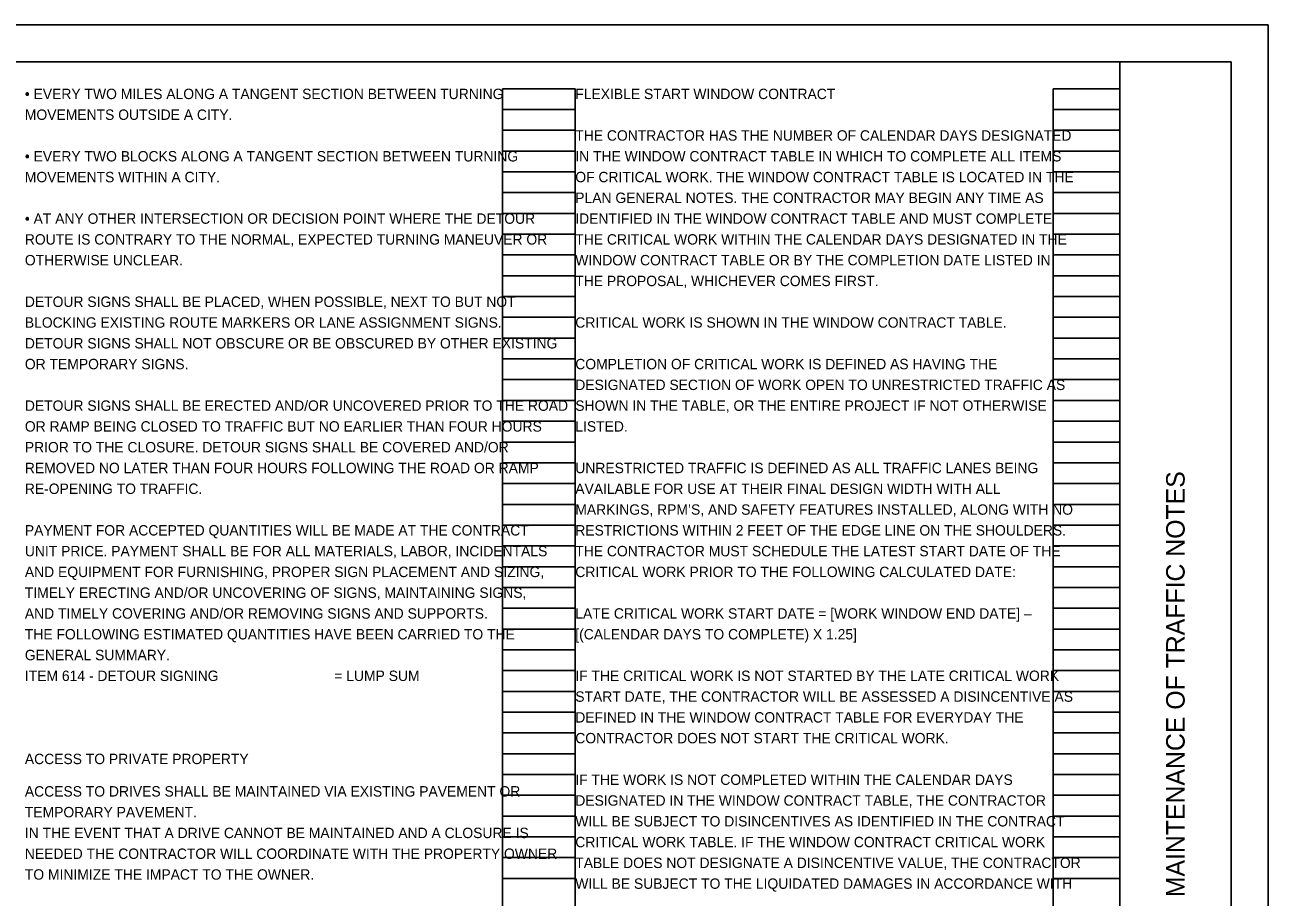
# Model space of a CAD drawing. Extents: x -1.3 to 43.7, y -2.4 to 22.
# Drawn here: x 17.24 to 34, y 10.25 to 22 of the extents above; entities that cross this region are included whole.
import ezdxf

# ---------------------------------------------------------------- set-up
doc = ezdxf.new("R2010")
doc.units = 0
for name, color, linetype in [('SH_Border', 7, 'Continuous'), ('SH_Cut_Line', 7, 'Continuous'), ('SH_Data', 7, 'Continuous'), ('SH_Text', 7, 'Continuous')]:
    doc.layers.add(name, color=color, linetype=linetype)

msp = doc.modelspace()

# ---------------------------------------------------------------- linework, layer by layer
at = {"layer": 'SH_Border'}
msp.add_line((32, 0.5), (32, 21.5), dxfattribs=at)
msp.add_lwpolyline([(1.5, 21.5), (33.5, 21.5), (33.5, 0.5), (1.5, 0.5)], close=True, dxfattribs=at)
at = {"layer": 'SH_Cut_Line'}
msp.add_lwpolyline([(0, 0), (34, 0), (34, 22), (0, 22)], close=True, dxfattribs=at)
at = {"layer": 'SH_Data'}
for p, q in [((23.68, 0.98), (23.68, 21.14)), ((23.68, 21.14), (24.66, 21.14)), ((24.66, 0.98), (24.66, 21.14)), ((31.1, 0.98), (31.1, 21.14)), ((31.1, 21.14), (32, 21.14)), ((32, 0.98), (32, 21.14)), ((23.68, 20.86), (24.66, 20.86)), ((31.1, 20.86), (32, 20.86)), ((23.68, 20.58), (24.66, 20.58)), ((31.1, 20.58), (32, 20.58)), ((23.68, 20.3), (24.66, 20.3)), ((31.1, 20.3), (32, 20.3)), ((23.68, 20.02), (24.66, 20.02)), ((31.1, 20.02), (32, 20.02)), ((23.68, 19.74), (24.66, 19.74)), ((31.1, 19.74), (32, 19.74)), ((23.68, 19.46), (24.66, 19.46)), ((31.1, 19.46), (32, 19.46)), ((23.68, 19.18), (24.66, 19.18)), ((31.1, 19.18), (32, 19.18)), ((23.68, 18.9), (24.66, 18.9)), ((31.1, 18.9), (32, 18.9)), ((23.68, 18.62), (24.66, 18.62)), ((31.1, 18.62), (32, 18.62)), ((23.68, 18.34), (24.66, 18.34)), ((31.1, 18.34), (32, 18.34)), ((23.68, 18.06), (24.66, 18.06)), ((31.1, 18.06), (32, 18.06)), ((23.68, 17.78), (24.66, 17.78)), ((31.1, 17.78), (32, 17.78)), ((23.68, 17.5), (24.66, 17.5)), ((31.1, 17.5), (32, 17.5)), ((23.68, 17.22), (24.66, 17.22)), ((31.1, 17.22), (32, 17.22)), ((23.68, 16.94), (24.66, 16.94)), ((31.1, 16.94), (32, 16.94)), ((23.68, 16.66), (24.66, 16.66)), ((31.1, 16.66), (32, 16.66)), ((23.68, 16.38), (24.66, 16.38)), ((31.1, 16.38), (32, 16.38)), ((23.68, 16.1), (24.66, 16.1)), ((31.1, 16.1), (32, 16.1)), ((23.68, 15.82), (24.66, 15.82)), ((31.1, 15.82), (32, 15.82)), ((23.68, 15.54), (24.66, 15.54)), ((31.1, 15.54), (32, 15.54)), ((23.68, 15.26), (24.66, 15.26)), ((31.1, 15.26), (32, 15.26)), ((23.68, 14.98), (24.66, 14.98)), ((31.1, 14.98), (32, 14.98)), ((23.68, 14.7), (24.66, 14.7)), ((31.1, 14.7), (32, 14.7)), ((23.68, 14.42), (24.66, 14.42)), ((31.1, 14.42), (32, 14.42)), ((23.68, 14.14), (24.66, 14.14)), ((31.1, 14.14), (32, 14.14)), ((23.68, 13.86), (24.66, 13.86)), ((31.1, 13.86), (32, 13.86)), ((23.68, 13.58), (24.66, 13.58)), ((31.1, 13.58), (32, 13.58)), ((23.68, 13.3), (24.66, 13.3)), ((31.1, 13.3), (32, 13.3)), ((23.68, 13.02), (24.66, 13.02)), ((31.1, 13.02), (32, 13.02)), ((23.68, 12.74), (24.66, 12.74)), ((31.1, 12.74), (32, 12.74)), ((23.68, 12.46), (24.66, 12.46)), ((31.1, 12.46), (32, 12.46)), ((23.68, 12.18), (24.66, 12.18)), ((31.1, 12.18), (32, 12.18)), ((23.68, 11.9), (24.66, 11.9)), ((31.1, 11.9), (32, 11.9)), ((23.68, 11.62), (24.66, 11.62)), ((31.1, 11.62), (32, 11.62)), ((23.68, 11.34), (24.66, 11.34)), ((31.1, 11.34), (32, 11.34)), ((23.68, 11.06), (24.66, 11.06)), ((31.1, 11.06), (32, 11.06)), ((23.68, 10.78), (24.66, 10.78)), ((31.1, 10.78), (32, 10.78)), ((23.68, 10.5), (24.66, 10.5)), ((31.1, 10.5), (32, 10.5))]:
    msp.add_line(p, q, dxfattribs=at)

# ---------------------------------------------------------------- texts
msp.add_text('MAINTENANCE OF TRAFFIC NOTES', height=0.25, rotation=90, dxfattribs=at).set_placement((32.875, 10.247))
at = {"layer": 'SH_Text'}
for s, p in [('• EVERY TWO MILES ALONG A TANGENT SECTION BETWEEN TURNING ', (17.24, 21)), ('FLEXIBLE START WINDOW CONTRACT', (24.66, 21)), ('MOVEMENTS OUTSIDE A CITY.', (17.24, 20.72)), ('THE CONTRACTOR HAS THE NUMBER OF CALENDAR DAYS DESIGNATED ', (24.66, 20.44)), ('• EVERY TWO BLOCKS ALONG A TANGENT SECTION BETWEEN TURNING ', (17.24, 20.16)), ('IN THE WINDOW CONTRACT TABLE IN WHICH TO COMPLETE ALL ITEMS ', (24.66, 20.16)), ('MOVEMENTS WITHIN A CITY.', (17.24, 19.88)), ('OF CRITICAL WORK. THE WINDOW CONTRACT TABLE IS LOCATED IN THE ', (24.66, 19.88)), ('PLAN GENERAL NOTES. THE CONTRACTOR MAY BEGIN ANY TIME AS ', (24.66, 19.6)), ('• AT ANY OTHER INTERSECTION OR DECISION POINT WHERE THE DETOUR ', (17.24, 19.32)), ('IDENTIFIED IN THE WINDOW CONTRACT TABLE AND MUST COMPLETE ', (24.66, 19.32)), ('ROUTE IS CONTRARY TO THE NORMAL, EXPECTED TURNING MANEUVER OR ', (17.24, 19.04)), ('THE CRITICAL WORK WITHIN THE CALENDAR DAYS DESIGNATED IN THE ', (24.66, 19.04)), ('OTHERWISE UNCLEAR.', (17.24, 18.76)), ('WINDOW CONTRACT TABLE OR BY THE COMPLETION DATE LISTED IN ', (24.66, 18.76)), ('THE PROPOSAL, WHICHEVER COMES FIRST.', (24.66, 18.48)), ('DETOUR SIGNS SHALL BE PLACED, WHEN POSSIBLE, NEXT TO BUT NOT ', (17.24, 18.2)), ('BLOCKING EXISTING ROUTE MARKERS OR LANE ASSIGNMENT SIGNS.  ', (17.24, 17.92)), ('CRITICAL WORK IS SHOWN IN THE WINDOW CONTRACT TABLE.', (24.66, 17.92)), ('DETOUR SIGNS SHALL NOT OBSCURE OR BE OBSCURED BY OTHER EXISTING ', (17.24, 17.64)), ('OR TEMPORARY SIGNS.', (17.24, 17.36)), ('COMPLETION OF CRITICAL WORK IS DEFINED AS HAVING THE ', (24.66, 17.36)), ('DESIGNATED SECTION OF WORK OPEN TO UNRESTRICTED TRAFFIC AS ', (24.66, 17.08)), ('DETOUR SIGNS SHALL BE ERECTED AND/OR UNCOVERED PRIOR TO THE ROAD ', (17.24, 16.8)), ('SHOWN IN THE TABLE, OR THE ENTIRE PROJECT IF NOT OTHERWISE ', (24.66, 16.8)), ('OR RAMP BEING CLOSED TO TRAFFIC BUT NO EARLIER THAN FOUR HOURS ', (17.24, 16.52)), ('LISTED.', (24.66, 16.52)), ('PRIOR TO THE CLOSURE. DETOUR SIGNS SHALL BE COVERED AND/OR ', (17.24, 16.24)), ('REMOVED NO LATER THAN FOUR HOURS FOLLOWING THE ROAD OR RAMP ', (17.24, 15.96)), ('UNRESTRICTED TRAFFIC IS DEFINED AS ALL TRAFFIC LANES BEING ', (24.66, 15.96)), ('RE-OPENING TO TRAFFIC. ', (17.24, 15.68)), ('AVAILABLE FOR USE AT THEIR FINAL DESIGN WIDTH WITH ALL ', (24.66, 15.68)), ('MARKINGS, RPM’S, AND SAFETY FEATURES INSTALLED, ALONG WITH NO ', (24.66, 15.4)), ('PAYMENT FOR ACCEPTED QUANTITIES WILL BE MADE AT THE CONTRACT ', (17.24, 15.12)), ('RESTRICTIONS WITHIN 2 FEET OF THE EDGE LINE ON THE SHOULDERS.', (24.66, 15.12)), ('UNIT PRICE. PAYMENT SHALL BE FOR ALL MATERIALS, LABOR, INCIDENTALS ', (17.24, 14.84)), ('THE CONTRACTOR MUST SCHEDULE THE LATEST START DATE OF THE ', (24.66, 14.84)), ('AND EQUIPMENT FOR FURNISHING, PROPER SIGN PLACEMENT AND SIZING, ', (17.24, 14.56)), ('CRITICAL WORK PRIOR TO THE FOLLOWING CALCULATED DATE:', (24.66, 14.56)), ('TIMELY ERECTING AND/OR UNCOVERING OF SIGNS, MAINTAINING SIGNS, ', (17.24, 14.28)), ('AND TIMELY COVERING AND/OR REMOVING SIGNS AND SUPPORTS. ', (17.24, 14)), ('LATE CRITICAL WORK START DATE = [WORK WINDOW END DATE] – ', (24.66, 14)), ('THE FOLLOWING ESTIMATED QUANTITIES HAVE BEEN CARRIED TO THE ', (17.24, 13.72)), ('[(CALENDAR DAYS TO COMPLETE) X 1.25]', (24.66, 13.72)), ('GENERAL SUMMARY.', (17.24, 13.44)), ('ITEM 614 - DETOUR SIGNING                              = LUMP SUM', (17.24, 13.16)), ('IF THE CRITICAL WORK IS NOT STARTED BY THE LATE CRITICAL WORK ', (24.66, 13.16)), ('START DATE, THE CONTRACTOR WILL BE ASSESSED A DISINCENTIVE AS ', (24.66, 12.88)), ('DEFINED IN THE WINDOW CONTRACT TABLE FOR EVERYDAY THE ', (24.66, 12.6)), ('CONTRACTOR DOES NOT START THE CRITICAL WORK.', (24.66, 12.32)), ('ACCESS TO PRIVATE PROPERTY', (17.24, 12.04)), ('IF THE WORK IS NOT COMPLETED WITHIN THE CALENDAR DAYS ', (24.66, 11.76)), ('ACCESS TO DRIVES SHALL BE MAINTAINED VIA EXISTING PAVEMENT OR ', (17.24, 11.603)), ('DESIGNATED IN THE WINDOW CONTRACT TABLE, THE CONTRACTOR ', (24.66, 11.48)), ('TEMPORARY PAVEMENT.', (17.24, 11.323)), ('WILL BE SUBJECT TO DISINCENTIVES AS IDENTIFIED IN THE CONTRACT ', (24.66, 11.2)), ('IN THE EVENT THAT A DRIVE CANNOT BE MAINTAINED AND A CLOSURE IS ', (17.24, 11.043)), ('CRITICAL WORK TABLE. IF THE WINDOW CONTRACT CRITICAL WORK ', (24.66, 10.92)), ('NEEDED THE CONTRACTOR WILL COORDINATE WITH THE PROPERTY OWNER ', (17.24, 10.763)), ('TABLE DOES NOT DESIGNATE A DISINCENTIVE VALUE, THE CONTRACTOR ', (24.66, 10.64)), ('TO MINIMIZE THE IMPACT TO THE OWNER.', (17.24, 10.483)), ('WILL BE SUBJECT TO THE LIQUIDATED DAMAGES IN ACCORDANCE WITH ', (24.66, 10.36))]:
    msp.add_text(s, height=0.14, dxfattribs=at).set_placement(p)

doc.saveas('drawing.dxf')
